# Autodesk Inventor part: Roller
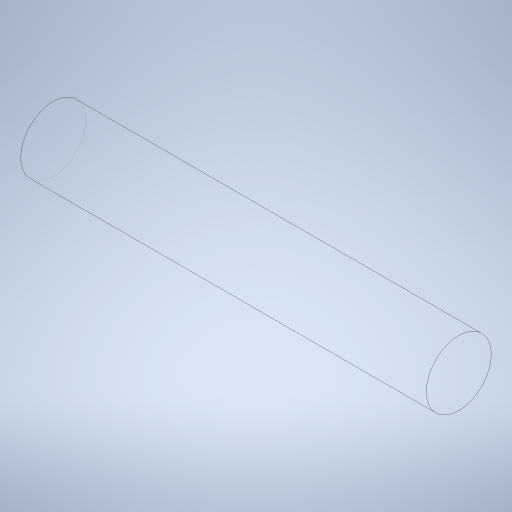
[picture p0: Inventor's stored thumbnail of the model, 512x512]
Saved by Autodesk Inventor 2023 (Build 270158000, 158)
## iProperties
Created: 2023-11
Part Number: Roller
Material: Aluminum 7075
Document SubType Name: Modeling
Designer: tornqvih
Density: 2.81 g/cm^3
Appearance: Semi-Polished
Author: tornqvih
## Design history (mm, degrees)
sketch "Sketch1"
  geometry: C1 r 24 at (0, 0); 1 further point
  constraints: 1 centre point, 1 coincident
  dimensions: "d0" = 48 diameter of C1
extrude "Extrusion1" new body sketch "Sketch1" distance "d1" = 300; taper "d2" = 0 deg
body "Solid1"
